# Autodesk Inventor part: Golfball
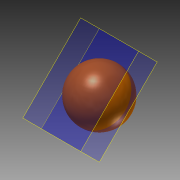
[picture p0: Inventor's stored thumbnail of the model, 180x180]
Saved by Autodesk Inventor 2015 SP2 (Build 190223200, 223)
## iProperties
Created: 2012-07
Part Number: Golfball
Material: Golfball
Document SubType Name: Modeling
Designer: rYan
Mass: 44.1276 g
Surface Area: 58.088 cm^2
Volume: 41.6298 cm^3
Density: 1.06 g/cm^3
Appearance: Allgemein
Author: rYan
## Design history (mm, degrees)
sketch "Skizze1"
  geometry: L1 (-21.5, 0)-(21.5, 0); L2 (-30.1, 0)-(30.1, 0) reference; A1 r 21.5 centre (0, 0) between (-21.5, 0) and (21.5, 0); 1 further point
  constraints: 2 end point, 2 point on circle, 1 centre point, 1 coincident, 1 collinear, 1 horizontal
  dimensions: "d0" = 43 diameter of A1
revolve "Umdrehung1" sketch "Skizze1" stored, may be unused: angle "d2" = 90 deg
workplane "Arbeitsebene2"
  workplane "Arbeitsebene1"
node "Volumenkörper1"
other parameters: "d3" = -45 deg
